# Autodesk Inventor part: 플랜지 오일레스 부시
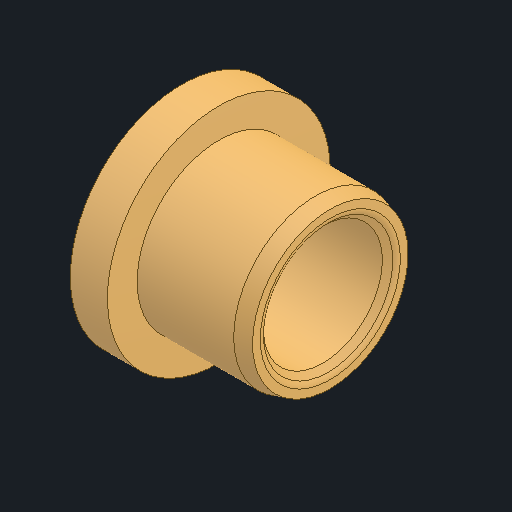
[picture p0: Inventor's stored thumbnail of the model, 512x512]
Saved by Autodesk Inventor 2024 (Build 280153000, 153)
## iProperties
Created: 2025-02
Part Number: 플랜지 오일레스 부시
Material: 구리, 합금
Document SubType Name: Modeling
Designer: kh_501
Density: 8.92 g/cm^3
Appearance: 기본값
Author: jhkim
Sending System: Autodesk Inventor 2025
Preprocessor: ST-DEVELOPER v20
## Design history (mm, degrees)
node "플랜지 오일레스 부시1"
node "솔리드2"
node "솔리드1"
